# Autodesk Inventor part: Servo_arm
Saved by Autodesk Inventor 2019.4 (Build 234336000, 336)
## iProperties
Created: 2020-04
Part Number: Servo_arm
Material: Generic
Document SubType Name: Modeling
Designer: Administrator
Density: 1 g/cm^3
Appearance: Default
Title: Servo_arm v5
Author: Administrator
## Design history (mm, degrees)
feature "Body1"
body "Solid1"
